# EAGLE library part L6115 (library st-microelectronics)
QUAD 100 V, DMOS SWITCH
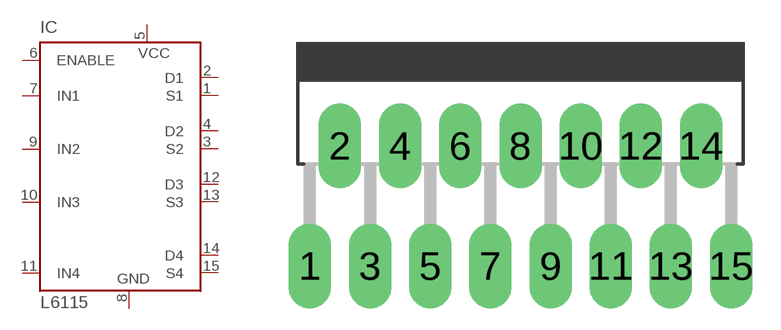
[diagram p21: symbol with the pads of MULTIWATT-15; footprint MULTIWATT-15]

Designator prefix IC

## L6115 (OC_FARNELL: unknown; OC_NEWARK: unknown)  [MULTIWATT-15]
1  S1  pas
2  D1  pas
3  S2  pas
4  D2  pas
5  VCC  pwr
6  ENABLE  in
7  IN1  in
8  GND  pwr
9  IN2  in
10  IN3  in
11  IN4  in
12  D3  pas
13  S3  pas
14  D4  pas
15  S4  pas

## Footprint MULTIWATT-15 (pad centres in mm)
Multiwatt 15 lead
drill 1.2 long: 1 -8.89,-7.62; 2 -7.62,-2.54; 3 -6.35,-7.62; 4 -5.08,-2.54; 5 -3.81,-7.62; 6 -2.54,-2.54; 7 -1.27,-7.62; 8 0,-2.54; 9 1.27,-7.62; 10 2.54,-2.54; 11 3.81,-7.62; 12 5.08,-2.54; 13 6.35,-7.62; 14 7.62,-2.54; 15 8.89,-7.62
